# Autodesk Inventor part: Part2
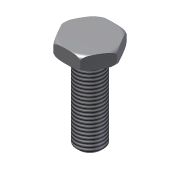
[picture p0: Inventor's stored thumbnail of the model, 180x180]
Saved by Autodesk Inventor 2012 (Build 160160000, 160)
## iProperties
Shininess: 77.0
Angle Display Precision: 2
Document Length Units: 11269
Document Angle Units: 11279
Document Time Units: 11290
Document Mass Units: 11283
Document Length Units Precision: 3
Document Angle Units Precision: 2
Created: 2002-01
Part Number: Part2
Document SubType Name: Modeling
Designer: ***
Density: 1 g/cm^3
Material: Default
Density: 0.0
Volumn: 0.0
Area: 0.0
PropertySet Name: Model Information
Control State: 0
Master: False
Checked Out: False
Author: ***
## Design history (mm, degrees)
sketch "Sketch1"
  geometry: C1 r 20 at (0, 0)
  constraints: 1 centre point
  dimensions: "d0" = 40 diameter of C1
extrude "Extrusion1" new body sketch "Sketch1" distance "d1" = 10; taper "d2" = 0 deg
fillet "Fillet1" dims "d3" = 3
sketch "Sketch3"
  geometry: L1 (20, 0)-(10, -17.321); L2 (10, -17.321)-(-10, -17.321); L3 (-10, -17.321)-(-20, 0); L4 (-20, 0)-(-10, 17.321); L5 (-10, 17.321)-(10, 17.321); L6 (10, 17.321)-(20, 0); C1 r 17 at (0, 0) reference; 1 further point
  constraints: 12 end point, 1 coincident, 11 other
extrude "Extrusion3" sketch "Sketch3" distance "d7" = 10; taper "d8" = 0 deg
sketch "Sketch2"
  geometry: C1 r 10 at (0, 0); 1 further point
  constraints: 1 centre point, 1 coincident
  dimensions: "d4" = 20 diameter of C1
extrude "Extrusion2" join sketch "Sketch2" distance "d5" = 60; taper "d6" = 0 deg
chamfer "Chamfer1" distance "d9" = 2; stored, may be unused: second distance "d10" = 2, angle "d13" = 45 deg
thread "Thread1" dims "d11" = 10, "d12" = 0
body "Solid1"
